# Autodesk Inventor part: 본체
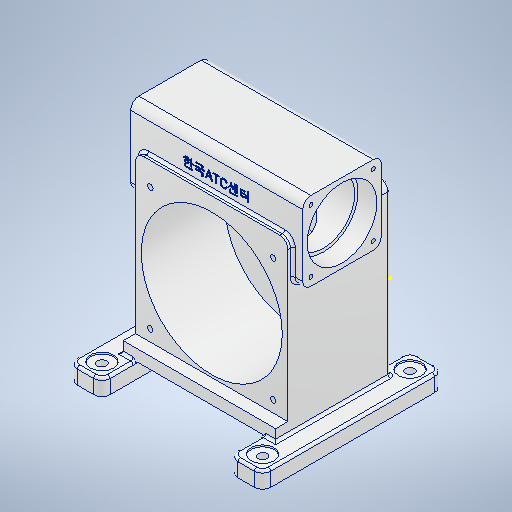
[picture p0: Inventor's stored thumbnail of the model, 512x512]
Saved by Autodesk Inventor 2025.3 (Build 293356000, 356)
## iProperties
Created: 2025-06
Part Number: 본체
Material: 알루미늄 6061
Document SubType Name: Modeling
Designer: PC-10
Density: 2.7 g/cm^3
Appearance: 알루미늄 - 평지
Mass: 7613.17 g
Surface Area: 3465.54 cm^2
Volume: 2819.69 cm^3
Author: PC-10
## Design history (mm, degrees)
sketch "스케치1"
  geometry: L1 (-93, -103)-(93, -103); L2 (93, -103)-(93, 103); L3 (93, 103)-(-93, 103); L4 (-93, 103)-(-93, -103); L5 (-93, -103)-(93, 103); L6 (93, -103)-(-93, 103); 1 further point
  constraints: 12 end point, 2 midpoint, 2 parallel, 1 horizontal, 1 perpendicular
  dimensions: "d0" = 186 distance of L2.end L3.end; "d1" = 206 distance of L1.end L2.end
extrude "돌출1" new body sketch "스케치1" distance "d2" = 125; taper "d3" = 0 deg
node "작업 평면2"
sketch "스케치3"
  geometry: C1 r 86 at (0, 0); 1 further point
  constraints: 1 centre point, 1 coincident
  dimensions: "d8" = 172 diameter of C1
extrude "돌출2" cut sketch "스케치3" distance "d9" = 102; taper "d10" = 0 deg
sketch "스케치4"
  geometry: L1 (-86, 23)-(86, 23) reference; L2 (103, 0)-(-103, 0) reference; L3 (0, 0)-(0, -17.431); L4 (31, 23)-(31, 7); L5 (31, 7)-(27, 7); L6 (27, 7)-(27, 4); L7 (27, 4)-(0, 4); L8 (0, 4)-(0, 23); 1 further point
  constraints: 12 end point, 3 perpendicular, 2 midpoint, 2 vertical, 1 point on line, 1 vertical alignment
  dimensions: "d11" = 62 diameter of L4 L3; "d12" = 54 diameter of L6 L3; "d13" = 3 distance between parallel lines of L5 L7; "d14" = 16 distance of L4.start L4.end
revolve "회전1" sketch "스케치4" stored, may be unused: angle "d15" = 90 deg
sketch "스케치6"
  geometry: L1 (148, 119)-(52, 119); L2 (52, 119)-(52, 23); L3 (52, 23)-(148, 23); L4 (148, 23)-(148, 119); L5 (-86, 23)-(86, 23) reference; L6 (103, 0)-(103, 125) reference; 1 further point
  constraints: 8 end point, 2 parallel, 1 horizontal, 1 horizontal alignment, 1 perpendicular
  dimensions: "d20" = 96 distance of L3.end L1.start; "d21" = 96 distance of L1.start L1.end; "d22" = 45 distance between parallel lines of L4 L6
extrude "돌출4" join sketch "스케치6" stored distance "d23" = 210; taper "d24" = 0 deg
sketch "스케치7"
  geometry: L1 (119, 52)-(119, 148) reference; L2 (119, 148)-(23, 148) reference; L3 (23, 148)-(23, 52) reference; L4 (23, 52)-(119, 52) reference; 4 further points
  constraints: 2 midpoint, 1 horizontal alignment, 1 vertical alignment
hole "구멍1" sketch "스케치7" at (71, 100) diameter "d25" = 77; stored, may be unused: countersink angle "d29" = 90 deg, drill point angle "d31" = 118 deg; dims "d26" = 13, "d27" = 85, "d28" = 23, "d30" = 16
sketch "스케치8"
  geometry: C1 r 38.5 at (-71, 100) reference; C2 r 42.5 at (-71, 100); 1 further point
  constraints: 1 centre point, 1 coincident
  dimensions: "d32" = 85 diameter of C2
extrude "돌출5" cut sketch "스케치8" distance "d33" = 23; taper "d34" = 0 deg
node "작업 평면3"
sketch "스케치9"
  geometry: L1 (-68.498, 52)-(68.498, 52) reference; A1 r 86 centre (0, 0) between (68.498, 52) and (-68.498, 52) reference; 1 further point
extrude "돌출6" cut sketch "스케치9" distance "d36" = 102; taper "d37" = 0 deg
node "작업 평면5"
node "작업 평면6"
node "작업 평면7"
node "작업 평면8"
sketch "스케치10"
  geometry: L1 (198, -6)-(12, -6) reference; L2 (12, -6)-(198, -6); L3 (198, -6)-(198, -21); L4 (198, -21)-(12, -21); L5 (12, -21)-(12, -6); 2 further points
  constraints: 8 end point, 2 parallel, 1 horizontal, 1 perpendicular
  dimensions: "d40" = 15 distance of L4.end L1.end
extrude "돌출7" join sketch "스케치10" distance "d41" = 14; taper "d42" = 0 deg
sketch "스케치11"
  geometry: 1 further point
node "작업 평면10"
sketch "스케치12"
  geometry: L1 (223, -62)-(183, -62); L2 (183, -62)-(183, 158); L3 (183, 158)-(223, 158); L4 (223, 158)-(223, -62); L5 (27, -62)-(-13, -62); L6 (-13, -62)-(-13, 158); L7 (-13, 158)-(27, 158); L8 (27, 158)-(27, -62); L9 (210, 0)-(210, 96) reference; 3 further points
  constraints: 16 end point, 4 parallel, 3 horizontal alignment, 2 horizontal, 2 midpoint, 2 perpendicular
  dimensions: "d45" = 40 distance of L2.end L3.end; "d46" = 236 distance between parallel lines of L6 L4; "d47" = 40 distance of L6.end L7.end; "d48" = 118 distance from line of point (105, 119) L4; "d49" = 220 distance of L3.end L1.start
extrude "돌출8" join sketch "스케치12" distance "d50" = 20; taper "d51" = 0 deg
sketch "스케치13"
  geometry: L1 (12, 119)-(27, 119) reference; L2 (27, 119)-(27, 158) reference; L3 (27, 158)-(-13, 158) reference; L4 (-13, 158)-(-13, -62) reference; L5 (-13, -62)-(27, -62) reference; L6 (27, -62)-(27, -21) reference; L7 (27, -21)-(12, -21) reference; L8 (12, 119)-(12, -21) reference; L9 (198, -21)-(183, -21) reference; L10 (183, -21)-(183, -62) reference; L11 (183, -62)-(223, -62) reference; L12 (223, -62)-(223, 158) reference; L13 (223, 158)-(183, 158) reference; L14 (183, 158)-(183, 119) reference; L15 (183, 119)-(198, 119) reference; L16 (198, 119)-(198, -21) reference; L17 (198, 119)-(12, 119) reference; L18 (0, 0)-(0, 96) reference; 7 further points
  constraints: 2 horizontal alignment, 2 midpoint, 2 vertical alignment
  dimensions: "d52" = 180 distance of point (7, -42) point (7, 138); "d53" = 196 distance of point (203, 138) point (7, 138); "d54" = 98 horizontal distance of point (105, 119) point (7, 138); "d55" = 90 vertical distance of point (0, 48) point (7, -42)
hole "구멍2" sketch "스케치13" at (7, 138), (7, -42), (203, -42), (203, 138) diameter "d56" = 11; stored, may be unused: countersink angle "d60" = 90 deg, drill point angle "d62" = 118 deg; dims "d57" = 6, "d58" = 28, "d59" = 2, "d61" = 8
sketch "스케치14"
  geometry: L1 (119, 52)-(119, 148) reference; L2 (119, 148)-(23, 148) reference; L3 (23, 148)-(23, 52) reference; L4 (23, 52)-(119, 52) reference; L5 (33, 62)-(109, 62); L6 (109, 62)-(109, 138); L7 (109, 138)-(33, 138); L8 (33, 138)-(33, 62); L9 (33, 62)-(109, 138); L10 (109, 62)-(33, 138); C1 r 42.5 at (71, 100) reference; 5 further points
  constraints: 12 end point, 4 coincident, 2 midpoint, 2 parallel, 1 horizontal, 1 perpendicular
  dimensions: "d63" = 76 distance of L6.end L7.end; "d64" = 76 distance of L5.end L6.end
hole "구멍3" sketch "스케치14" at (109, 138), (33, 138), (33, 62), (109, 62) diameter "d65" = 4.917; stored, may be unused: countersink angle "d69" = 90 deg, drill point angle "d71" = 118 deg; dims "d66" = 12, "d67" = 28, "d68" = 2, "d70" = 14
node "작업 평면11"
sketch "스케치15"
  geometry: L1 (-75, -75)-(75, -75); L2 (75, -75)-(75, 75); L3 (75, 75)-(-75, 75); L4 (-75, 75)-(-75, -75); L5 (-75, -75)-(75, 75); L6 (75, -75)-(-75, 75); 5 further points
  constraints: 12 end point, 4 coincident, 2 midpoint, 2 parallel, 1 horizontal, 1 perpendicular
  dimensions: "d72" = 150 distance of L3.end L2.end; "d73" = 150 distance of L2.end L1.end
hole "구멍4" sketch "스케치15" at (75, 75), (75, -75), (-75, -75), (-75, 75) diameter "d74" = 6.647; stored, may be unused: countersink angle "d78" = 90 deg, drill point angle "d80" = 118 deg; dims "d75" = 16, "d76" = 4, "d77" = 2, "d79" = 18
fillet "모깎기1" dims "d81" = 10
fillet "모깎기2" dims "d82" = 3
fillet "모깎기3" dims "d83" = 3
sketch "스케치16"
  geometry: L1 (210, 10)-(0, 10) reference; 3 further points
  constraints: 1 midpoint, 1 vertical alignment, 1 other
  dimensions: "d84" = 30 distance from line of L1 point (105, -20)
feature "엠보싱1" sketch "스케치16" dims "d0" = 186, "d1" = 206, "d11" = 62, "d12" = 54, "d13" = 3, "d14" = 16, "d85" = 0.5, "d86" = 0
node "솔리드1"
mirror "미러1"
node "투영된 루프2"
node "투영된 루프3"
node "투영된 루프4"
node "투영된 루프5"
node "투영된 루프6"
feature "A9D066F2-1C7D-4E18-AEED-F7BC21143FA4" dims "d25" = 77, "d26" = 13, "d27" = 85, "d28" = 23, "d29" = 90 deg, "d30" = 16, "d31" = 118 deg
other parameters: "d7" = -123, "d39" = -189, "d44" = -271
